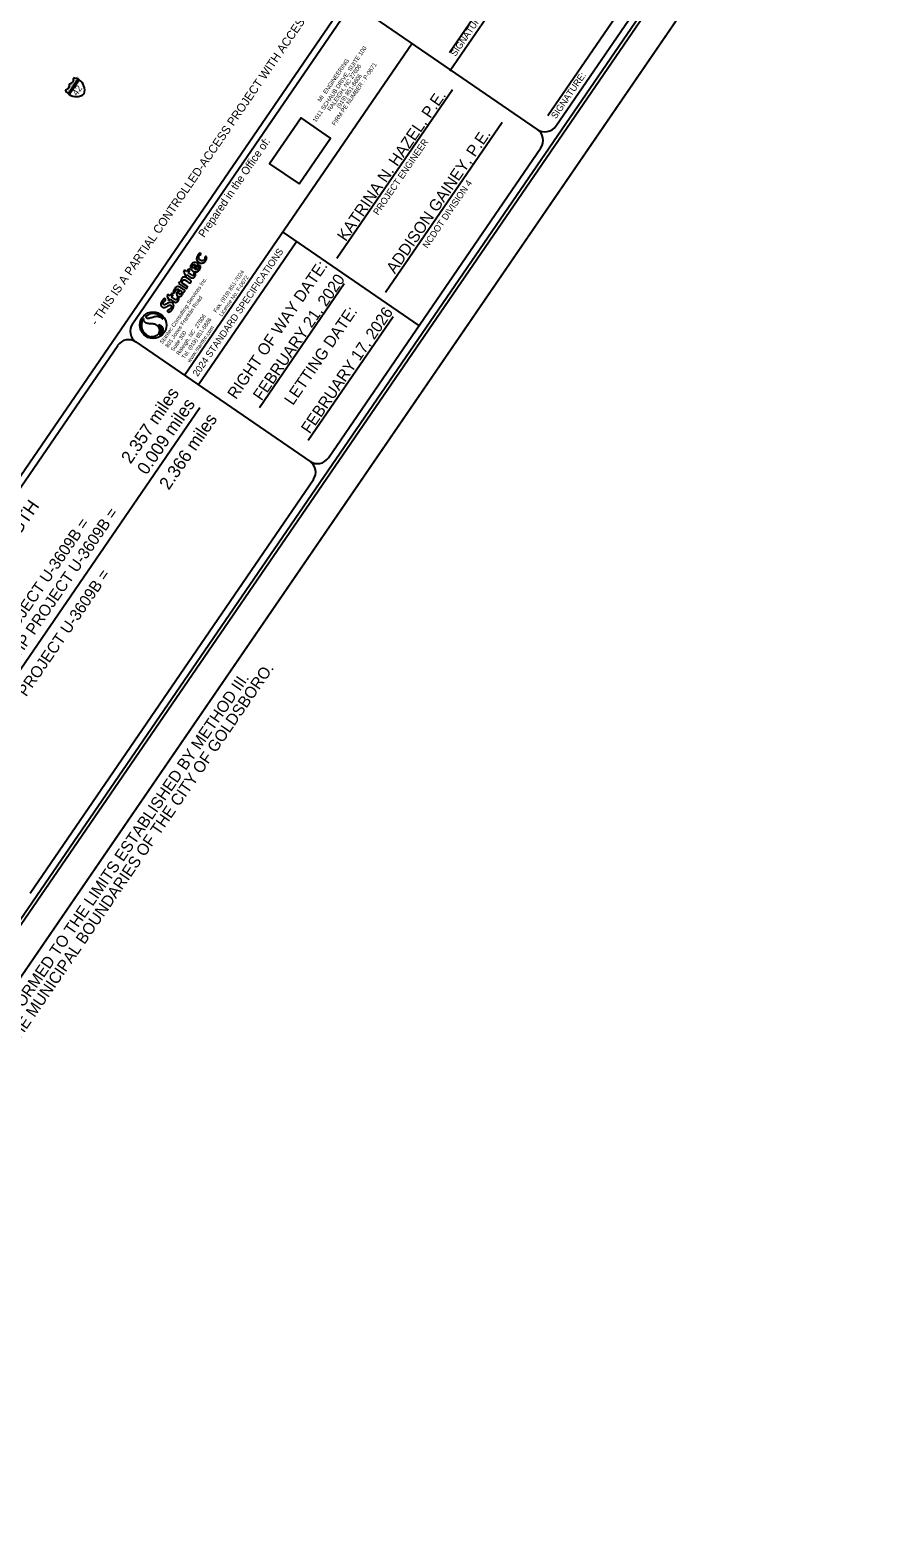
# Model space of a CAD drawing. Extents: x 2312641 to 2338852, y 590461 to 618614.
# Drawn here: x 2329705 to 2338852, y 590461 to 606464 of the extents above; entities that cross this region are included whole.
import ezdxf

# ---------------------------------------------------------------- set-up
doc = ezdxf.new("R2010")
doc.units = 0
for name, color, linetype in [('Default', 7, 'Continuous'), ('Exist Other Culture Area Outline Text', 7, 'Continuous'), ('Exist Other Culture Sign Post Text', 7, 'Continuous'), ('Exist Property Iron Pin Cogo Number', 7, 'Continuous'), ('Exist Structure Minor Head and End Wall Text', 7, 'Continuous'), ('Exist Utilities Power Joint Use Telephone CELL', 7, 'Continuous'), ('Exist Utilities Power Joint Use Telephone Text', 7, 'Continuous'), ('Exist Utilities Power Pole CELL', 7, 'Continuous'), ('Exist Vegetation Woods Line Text', 7, 'Continuous')]:
    doc.layers.add(name, color=color, linetype=linetype)

msp = doc.modelspace()

# ---------------------------------------------------------------- linework, layer by layer
at = {"layer": 'Default'}
for p, q in [((2330111, 605788), (2330216, 605942)), ((2330216, 605942), (2330111, 605788)), ((2330111, 605788), (2330216, 605942)), ((2330119, 605782), (2330225, 605936)), ((2330225, 605936), (2330119, 605782)), ((2330119, 605782), (2330225, 605936)), ((2330111, 605788), (2330111, 605788)), ((2328591, 598208), (2331505, 602460))]:
    msp.add_line(p, q, dxfattribs=at)
for centre, radius, start, end in [((2330071, 605881), 52.4, 277.8759, 14.4267), ((2330115, 605946), 52.4, 276.7255, 13.2763), ((2330151, 605826), 133, 60.3904, 83.4009), ((2330151, 605826), 133, 56.1286, 60.3887), ((2330151, 605826), 133, 342.779, 56.1166), ((2330195, 605891), 133, 207.7515, 230.7405), ((2330195, 605891), 133, 230.7617, 235.0231), ((2330195, 605891), 133, 235.0416, 308.3732)]:
    msp.add_arc(centre, radius, start, end, dxfattribs=at)
at = {"layer": 'Exist Other Culture Area Outline Text'}
for p, q in [((2331463, 603969), (2331440, 603934)), ((2331454, 603925), (2331493, 603983)), ((2331521, 604083), (2331509, 604098)), ((2331294, 603794), (2331280, 603775)), ((2331304, 603789), (2331294, 603794)), ((2331342, 603919), (2331333, 603892)), ((2331333, 603892), (2331352, 603879)), ((2331367, 603902), (2331342, 603919)), ((2331352, 603879), (2331342, 603865)), ((2331342, 603865), (2331358, 603854)), ((2331358, 603854), (2331368, 603868)), ((2331388, 603932), (2331367, 603902)), ((2331383, 603891), (2331400, 603915)), ((2331423, 603863), (2331383, 603891)), ((2331400, 603915), (2331388, 603932)), ((2331165, 603661), (2331156, 603634)), ((2331156, 603634), (2331175, 603621)), ((2331190, 603643), (2331165, 603661)), ((2331211, 603673), (2331190, 603643)), ((2331206, 603632), (2331223, 603657)), ((2331246, 603605), (2331206, 603632)), ((2331223, 603657), (2331211, 603673)), ((2331223, 603679), (2331241, 603676)), ((2331280, 603775), (2331353, 603725)), ((2331295, 603703), (2331313, 603691)), ((2331369, 603747), (2331320, 603780)), ((2331145, 603599), (2331133, 603616)), ((2331175, 603621), (2331165, 603606)), ((2331165, 603606), (2331181, 603595)), ((2331181, 603595), (2331191, 603610))]:
    msp.add_line(p, q, dxfattribs=at)
for points in [[(2330909, 603404), (2330909, 603404)], [(2330969, 603449), (2330969, 603449)]]:
    msp.add_lwpolyline(points, dxfattribs=at)
msp.add_circle((2331010, 603332), 141, dxfattribs=at)
for start, end in [(144.3743, 259.2922), (144.3679, 144.3743), (29.3892, 109.0404), (302.7261, 307.0657)]:
    msp.add_arc((2331010, 603332), 124, start, end, dxfattribs=at)
for points, degree in [([(2331493, 603983), (2331491, 603984), (2331486, 603988), (2331476, 603994), (2331465, 603998), (2331453, 603999), (2331443, 603998), (2331434, 603994), (2331424, 603988), (2331417, 603978), (2331410, 603969), (2331407, 603957), (2331406, 603946), (2331408, 603935), (2331413, 603925), (2331419, 603917), (2331428, 603910), (2331437, 603903), (2331447, 603899), (2331458, 603897), (2331469, 603897), (2331480, 603901), (2331492, 603908), (2331501, 603919), (2331508, 603930), (2331512, 603940), (2331514, 603950), (2331513, 603958), (2331509, 603963), (2331505, 603965), (2331500, 603965), (2331497, 603963), (2331495, 603960), (2331493, 603955), (2331493, 603949), (2331493, 603943), (2331490, 603936), (2331486, 603930), (2331481, 603926), (2331475, 603923), (2331469, 603921), (2331462, 603922), (2331457, 603923), (2331454, 603924), (2331454, 603925)], 3), ([(2331440, 603934), (2331439, 603935), (2331437, 603936), (2331434, 603939), (2331430, 603943), (2331427, 603949), (2331427, 603955), (2331429, 603963), (2331433, 603969), (2331438, 603973), (2331445, 603976), (2331452, 603975), (2331458, 603973), (2331462, 603970), (2331463, 603969)], 3), ([(2331509, 604098), (2331507, 604097), (2331501, 604094), (2331492, 604087), (2331483, 604076), (2331476, 604063), (2331472, 604048), (2331471, 604034), (2331475, 604021), (2331483, 604010), (2331493, 604000), (2331505, 603994), (2331518, 603990), (2331530, 603991), (2331542, 603994), (2331555, 604002), (2331566, 604013), (2331574, 604026), (2331578, 604037), (2331579, 604048), (2331578, 604056), (2331574, 604060), (2331570, 604061), (2331566, 604061), (2331563, 604059), (2331561, 604057), (2331559, 604053), (2331560, 604048), (2331558, 604042), (2331557, 604035), (2331553, 604029), (2331548, 604022), (2331540, 604018), (2331532, 604016), (2331523, 604016), (2331515, 604020), (2331507, 604024), (2331501, 604031), (2331497, 604038), (2331495, 604045), (2331494, 604053), (2331496, 604061), (2331500, 604068), (2331506, 604075), (2331513, 604080), (2331518, 604082), (2331521, 604083)], 3), ([(2331320, 603780), (2331320, 603781), (2331320, 603783), (2331320, 603789), (2331320, 603796), (2331323, 603803), (2331327, 603809), (2331333, 603814), (2331340, 603815), (2331347, 603814), (2331355, 603810), (2331365, 603802), (2331378, 603794), (2331389, 603786), (2331397, 603781), (2331402, 603781), (2331409, 603783), (2331412, 603789), (2331414, 603795), (2331414, 603801), (2331409, 603806), (2331398, 603813), (2331385, 603822), (2331370, 603832), (2331362, 603838), (2331353, 603843), (2331346, 603844), (2331337, 603844), (2331328, 603841), (2331319, 603835), (2331313, 603826), (2331307, 603818), (2331305, 603809), (2331303, 603800), (2331304, 603793), (2331304, 603790), (2331304, 603789)], 3), ([(2331368, 603868), (2331382, 603859), (2331397, 603848), (2331414, 603837), (2331418, 603835), (2331425, 603833), (2331431, 603833), (2331436, 603835), (2331440, 603836), (2331446, 603840), (2331452, 603847), (2331456, 603855), (2331461, 603863), (2331462, 603871), (2331461, 603877), (2331458, 603882), (2331455, 603885), (2331452, 603886), (2331449, 603886), (2331447, 603885), (2331445, 603883), (2331443, 603881), (2331442, 603878), (2331443, 603875), (2331443, 603871), (2331442, 603867), (2331441, 603864), (2331439, 603861), (2331435, 603859), (2331432, 603859), (2331427, 603860), (2331425, 603862), (2331423, 603863)], 3), ([(2331191, 603610), (2331205, 603600), (2331220, 603590), (2331237, 603578), (2331241, 603576), (2331248, 603574), (2331254, 603575), (2331259, 603576), (2331263, 603578), (2331269, 603582), (2331275, 603589), (2331279, 603596), (2331284, 603605), (2331285, 603612), (2331284, 603619), (2331282, 603624), (2331278, 603626), (2331275, 603628), (2331272, 603627), (2331270, 603626), (2331268, 603624), (2331266, 603622), (2331265, 603619), (2331266, 603616), (2331266, 603613), (2331265, 603609), (2331264, 603605), (2331262, 603602), (2331258, 603601), (2331255, 603600), (2331250, 603602), (2331248, 603603), (2331246, 603605)], 3), ([(2331326, 603685), (2331326, 603685), (2331328, 603684), (2331333, 603683), (2331337, 603684), (2331343, 603687), (2331346, 603693), (2331349, 603698), (2331346, 603703), (2331342, 603705), (2331337, 603708), (2331322, 603716), (2331308, 603727), (2331291, 603738), (2331282, 603741), (2331272, 603742), (2331264, 603741), (2331255, 603736), (2331246, 603728), (2331237, 603717), (2331230, 603705), (2331225, 603692), (2331224, 603683), (2331223, 603679)], 3), ([(2331241, 603676), (2331241, 603678), (2331242, 603682), (2331244, 603688), (2331247, 603696), (2331250, 603702), (2331255, 603708), (2331260, 603712), (2331266, 603715), (2331273, 603716), (2331278, 603715), (2331280, 603713), (2331281, 603712)], 3), ([(2331281, 603712), (2331280, 603711), (2331277, 603706), (2331272, 603697), (2331266, 603687), (2331261, 603676), (2331259, 603665), (2331260, 603654), (2331267, 603644), (2331276, 603639), (2331284, 603635), (2331293, 603635), (2331303, 603638), (2331313, 603645), (2331320, 603654), (2331325, 603664), (2331327, 603672), (2331327, 603679), (2331326, 603683), (2331326, 603685)], 3), ([(2331313, 603691), (2331313, 603690), (2331313, 603687), (2331312, 603681), (2331311, 603674), (2331307, 603668), (2331303, 603664), (2331298, 603662), (2331294, 603662), (2331290, 603662), (2331286, 603665), (2331283, 603668), (2331281, 603672), (2331281, 603677), (2331282, 603682), (2331285, 603688), (2331289, 603694), (2331292, 603699), (2331294, 603702), (2331295, 603703)], 3), ([(2331353, 603725), (2331354, 603724), (2331357, 603723), (2331362, 603722), (2331368, 603724), (2331372, 603730), (2331375, 603736), (2331374, 603742), (2331371, 603745), (2331369, 603747), (2331369, 603747)], 3), ([(2331133, 603616), (2331132, 603615), (2331126, 603612), (2331118, 603605), (2331110, 603595), (2331103, 603586), (2331098, 603578), (2331094, 603569), (2331092, 603559), (2331092, 603549), (2331095, 603539), (2331100, 603532), (2331106, 603527), (2331111, 603523), (2331118, 603521), (2331124, 603520), (2331130, 603520), (2331136, 603521), (2331142, 603523), (2331149, 603526), (2331156, 603530), (2331164, 603535), (2331172, 603540), (2331179, 603544), (2331186, 603546), (2331192, 603546), (2331197, 603544), (2331200, 603542), (2331204, 603537), (2331205, 603531), (2331203, 603523), (2331200, 603515), (2331194, 603508), (2331188, 603502), (2331181, 603498), (2331177, 603495), (2331172, 603494), (2331169, 603492), (2331166, 603490), (2331164, 603487), (2331163, 603484), (2331163, 603480), (2331165, 603476), (2331168, 603474), (2331172, 603472), (2331177, 603472), (2331185, 603474), (2331195, 603480), (2331206, 603488), (2331213, 603499), (2331220, 603508), (2331224, 603517), (2331227, 603526), (2331229, 603536), (2331228, 603546), (2331225, 603557), (2331218, 603565), (2331211, 603570), (2331204, 603574), (2331196, 603575), (2331189, 603575), (2331180, 603573), (2331172, 603569), (2331164, 603565), (2331155, 603560), (2331146, 603554), (2331138, 603550), (2331131, 603548), (2331126, 603549), (2331122, 603552), (2331119, 603555), (2331117, 603560), (2331117, 603565), (2331119, 603571), (2331122, 603577), (2331126, 603582), (2331131, 603587), (2331136, 603592), (2331141, 603596), (2331144, 603598), (2331145, 603599)], 3), ([(2330909, 603404), (2330908, 603401), (2330905, 603395), (2330908, 603382), (2330916, 603367), (2330931, 603358), (2330949, 603354), (2330967, 603352), (2330987, 603350), (2331007, 603349), (2331026, 603346), (2331043, 603338), (2331057, 603325), (2331069, 603311), (2331076, 603294), (2331077, 603276), (2331074, 603260), (2331070, 603247), (2331062, 603235), (2331050, 603223), (2331035, 603214), (2331014, 603208), (2330997, 603209), (2330987, 603210)], 3), ([(2330909, 603404), (2330909, 603404), (2330909, 603404), (2330909, 603404)], 2), ([(2331118, 603393), (2331115, 603396), (2331109, 603402), (2331098, 603409), (2331088, 603415), (2331077, 603418), (2331065, 603422), (2331050, 603424), (2331034, 603422), (2331015, 603419), (2330996, 603412), (2330976, 603406), (2330960, 603401), (2330947, 603404), (2330940, 603409), (2330937, 603416), (2330937, 603423), (2330941, 603430), (2330948, 603437), (2330957, 603443), (2330965, 603447), (2330969, 603449)], 3), ([(2331070, 603339), (2331073, 603338), (2331081, 603335), (2331092, 603328), (2331103, 603318), (2331110, 603304), (2331114, 603289), (2331111, 603273), (2331105, 603258), (2331096, 603244), (2331088, 603237), (2331085, 603233)], 3), ([(2331077, 603227), (2331079, 603230), (2331084, 603235), (2331089, 603247), (2331094, 603260), (2331095, 603274), (2331095, 603288), (2331091, 603303), (2331086, 603318), (2331078, 603330), (2331072, 603336), (2331070, 603339)], 3)]:
    msp.add_open_spline(points, degree=degree, dxfattribs=at)
at = {"layer": 'Exist Other Culture Sign Post Text'}
msp.add_line((2325524, 590461), (2338852, 609909), dxfattribs=at)
at = {"layer": 'Exist Property Iron Pin Cogo Number'}
for p, q in [((2324878, 594842), (2336116, 611241)), ((2334159, 606032), (2335905, 608581)), ((2334157, 606227), (2335298, 607893)), ((2335201, 605558), (2336321, 607192)), ((2335090, 605409), (2333242, 606676)), ((2330792, 603348), (2333048, 606639)), ((2333759, 606322), (2331345, 602799)), ((2332961, 604042), (2334189, 605834)), ((2333477, 603682), (2334714, 605486)), ((2332386, 604319), (2333833, 603327)), ((2332534, 604218), (2331492, 602698)), ((2333039, 603770), (2332138, 602456)), ((2332234, 603780), (2332234, 603780)), ((2333557, 603421), (2332657, 602108)), ((2330828, 603154), (2332676, 601887)), ((2327626, 598729), (2330634, 603117)), ((2332588, 603112), (2332588, 603112))]:
    msp.add_line(p, q, dxfattribs=at)
for points in [[(2326637, 592703), (2338350, 609794)], [(2335285, 605446), (2336866, 607753)], [(2332871, 601924), (2335126, 605215)], [(2329705, 597304), (2332713, 601693)]]:
    msp.add_lwpolyline(points, dxfattribs=at)
for centre, start, end in [((2335169, 605525), 235.5761, 325.5761), ((2335010, 605294), 325.5761, 55.5761), ((2330907, 603269), 145.5761, 235.5761), ((2330749, 603038), 55.5761, 145.5761), ((2332755, 602003), 235.5761, 325.5761), ((2332596, 601772), 325.5761, 55.5761)]:
    msp.add_arc(centre, 140, start, end, dxfattribs=at)
at = {"layer": 'Exist Utilities Power Joint Use Telephone CELL'}
msp.add_lwpolyline([(2326149, 618614), (2312821, 599167), (2325524, 590461), (2338852, 609909)], close=True, dxfattribs=at)
at = {"layer": 'Exist Utilities Power Joint Use Telephone Text'}
msp.add_lwpolyline([(2325368, 590789), (2338557, 610034), (2326373, 618385), (2313184, 599139)], close=True, dxfattribs=at)
at = {"layer": 'Exist Utilities Power Pole CELL'}
msp.add_lwpolyline([(2332559, 604831), (2332894, 605319), (2332582, 605533), (2332247, 605045)], close=True, dxfattribs=at)

# ---------------------------------------------------------------- texts
at = {"layer": 'Default'}
for s, height, rotation, p in [('INTERSTATE', 23.4, 55.5761, (2330112, 605797)), ('42', 70.3, 55.5761, (2330203, 605762)), ('2.357 miles', 135, 55.6077, (2330771, 601852)), ('0.009 miles', 135, 55.6077, (2330941, 601735)), ('2.366 miles', 135, 55.6077, (2331176, 601575)), ('LENGTH STRUCTURES TIP PROJECT U-3609B =', 121.5, 55.6077, (2328530, 598255)), ('LENGTH ROADWAY TIP PROJECT U-3609B =', 121.5, 55.6077, (2328377, 598368)), ('TOTAL LENGTH TIP PROJECT U-3609B =', 121.5, 55.6077, (2328775, 598086))]:
    msp.add_text(s, height=height, rotation=rotation, dxfattribs=at).set_placement(p)
at = {"layer": 'Exist Other Culture Area Outline Text'}
for s, height, rotation, p in [('1011 SCHAUB DRIVE, SUITE 100', 45.01, 55.5757, (2332737, 605482)), ('MI  ENGINEERING', 45.01, 55.5761, (2332789, 605697)), ('RALEIGH, NC 27606', 45.01, 55.5758, (2332892, 605599)), ('FIRM PE NUMBER : P-0671', 45.01, 55.5758, (2332940, 605447)), ('(919) 851-6606', 45.01, 55.5758, (2332989, 605630)), ('Stantec Consulting Services Inc.', 42.26, 55.6077, (2331112, 603130)), ('Fax. (919) 851-7024', 42.26, 55.6077, (2331681, 603462)), ('License No. F-0672', 42.26, 55.6077, (2331740, 603421)), ('801 Jones Franklin Road', 42.26, 55.6077, (2331170, 603090)), ('Raleigh, NC  27606', 42.26, 55.6077, (2331286, 603010)), ('Tel. (919) 851-6866', 42.26, 55.6077, (2331344, 602970)), ('www.stantec.com', 42.26, 55.6077, (2331402, 602931)), ('Suite 300', 42.3, 55.6077, (2331228, 603050))]:
    msp.add_text(s, height=height, rotation=rotation, dxfattribs=at).set_placement(p)
at = {"layer": 'Exist Property Iron Pin Cogo Number'}
for s, height, p in [('SIGNATURE:', 70, (2334220, 606179)), ('SIGNATURE:', 70, (2335286, 605516)), ('Prepared in the Office of:', 83.99, (2331552, 604256)), ('PROJECT ENGINEER', 69.99, (2333398, 604495)), ('NCDOT DIVISION 4', 69.99, (2333922, 604143)), ('2024 STANDARD SPECIFICATIONS', 72.8, (2331483, 602781)), ('RIGHT OF WAY DATE: ', 122.5, (2331890, 602537)), ('LETTING DATE:', 122.5, (2332494, 602474)), ('PROJECT LENGTH', 139.99, (2328857, 600026))]:
    msp.add_text(s, height=height, rotation=55.5761, dxfattribs=at).set_placement(p)
at = {"layer": 'Exist Structure Minor Head and End Wall Text'}
for s, p in [('A PORTION OF THIS PROJECT IS WITHIN THE MUNICIPAL BOUNDARIES OF THE CITY OF GOLDSBORO.', (2327688, 592968)), ('CLEARING ON THIS PROJECT SHALL BE PERFORMED TO THE LIMITS ESTABLISHED BY METHOD III.', (2327558, 593058))]:
    msp.add_text(s, height=122.5, rotation=55.5761, dxfattribs=at).set_placement(p)
at = {"layer": 'Exist Utilities Power Pole CELL'}
msp.add_text('- THIS IS A PARTIAL CONTROLLED-ACCESS PROJECT WITH ACCESS BEING LIMITED TO POINTS AS SHOWN ON THE PLANS. ', height=90, rotation=55.5761, dxfattribs=at).set_placement((2330411, 603322))
at = {"layer": 'Exist Vegetation Woods Line Text'}
for s, p in [('KATRINA N. HAZEL, P.E.', (2333056, 604213)), ('ADDISON GAINEY, P.E.', (2333577, 603870)), ('FEBRUARY 21, 2020', (2332162, 602522)), ('FEBRUARY 17, 2026', (2332672, 602172))]:
    msp.add_text(s, height=122.5, rotation=55.5761, dxfattribs=at).set_placement(p)

doc.saveas('drawing.dxf')
